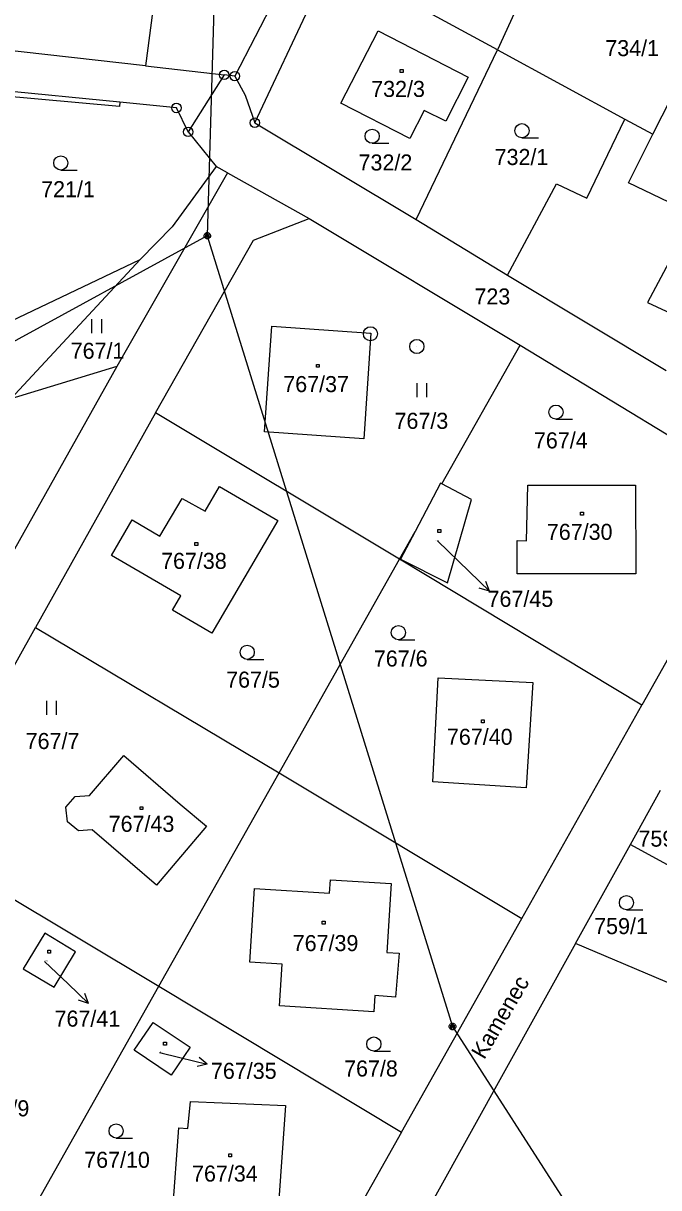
# Model space of a CAD drawing. Extents: x -468021 to -466942, y -1130484 to -1128584.
# Drawn here: x -467079.9 to -467012.6, y -1128824.5 to -1128701.2 of the extents above; entities that cross this region are included whole.
import ezdxf

# ---------------------------------------------------------------- set-up
doc = ezdxf.new("R2010")
doc.units = 0
doc.layers.add('DKM', color=7, linetype='Continuous')

msp = doc.modelspace()

# ---------------------------------------------------------------- linework, layer by layer
at = {"layer": 'DKM'}
for p, q in [((-467058.09, -1128643.52), (-467060.41, -1128723.66)), ((-467062.73, -1128674.01), (-467066.96, -1128705.68)), ((-467047.04, -1128686.61), (-467057.5, -1128706.75)), ((-467024.44, -1128692.54), (-467029.67, -1128703.98)), ((-467055.38, -1128711.69), (-467047.24, -1128694.42)), ((-467029.67, -1128703.98), (-467047.24, -1128694.42)), ((-467069.67, -1128709.53), (-467164, -1128700.1)), ((-467046.25, -1128709.61), (-467042.32, -1128701.97)), ((-467042.32, -1128701.97), (-467032.77, -1128706.88)), ((-467066.96, -1128705.68), (-467084.53, -1128703.69)), ((-467038.3, -1128721.94), (-467029.67, -1128703.98)), ((-467029.67, -1128703.98), (-467016.2, -1128711.3)), ((-467066.96, -1128705.68), (-467058.61, -1128706.63)), ((-467039.98, -1128706.07), (-467039.68, -1128706.07)), ((-467039.98, -1128706.37), (-467039.98, -1128706.07)), ((-467039.68, -1128706.07), (-467039.68, -1128706.37)), ((-467058.61, -1128706.63), (-467062.44, -1128712.66)), ((-467057.5, -1128706.75), (-467058.61, -1128706.63)), ((-467057.5, -1128706.75), (-467056.38, -1128708.77)), ((-467039.68, -1128706.37), (-467039.98, -1128706.37)), ((-467032.77, -1128706.88), (-467035.15, -1128711.51)), ((-467013.23, -1128712.92), (-467010.27, -1128707.07)), ((-467069.72, -1128709.99), (-467084.9, -1128708.58)), ((-467069.67, -1128709.53), (-467069.72, -1128709.99)), ((-467063.67, -1128710.13), (-467069.67, -1128709.53)), ((-467056.38, -1128708.77), (-467055.38, -1128711.69)), ((-467038.97, -1128713.35), (-467046.25, -1128709.61)), ((-467062.44, -1128712.66), (-467063.67, -1128710.13)), ((-467037.45, -1128710.39), (-467038.97, -1128713.35)), ((-467035.15, -1128711.51), (-467037.45, -1128710.39)), ((-467055.38, -1128711.69), (-467038.3, -1128721.94)), ((-467020.22, -1128719.68), (-467016.2, -1128711.3)), ((-467016.2, -1128711.3), (-467013.23, -1128712.92)), ((-467062.44, -1128712.66), (-467059.46, -1128716.33)), ((-467027.09, -1128713.29), (-467025.34, -1128713.29)), ((-467015.82, -1128718.04), (-467013.23, -1128712.92)), ((-467042.95, -1128713.87), (-467041.2, -1128713.87)), ((-467075.92, -1128716.7), (-467074.17, -1128716.7)), ((-467058.25, -1128717.01), (-467069.98, -1128737.5)), ((-467059.46, -1128716.33), (-467064.12, -1128722.7)), ((-467058.25, -1128717.01), (-467059.46, -1128716.33)), ((-467058.25, -1128717.01), (-467049.63, -1128721.85)), ((-467028.6, -1128727.82), (-467023.42, -1128718.15)), ((-467023.42, -1128718.15), (-467020.22, -1128719.68)), ((-467009.33, -1128721.17), (-467015.82, -1128718.04)), ((-467055.51, -1128724.12), (-467049.63, -1128721.85)), ((-467049.63, -1128721.85), (-467027.27, -1128735.26)), ((-467038.3, -1128721.94), (-467028.6, -1128727.82)), ((-467064.12, -1128722.7), (-467067.5, -1128726.17)), ((-467060.74, -1128723.59), (-467060.68, -1128723.46)), ((-467060.68, -1128723.46), (-467060.61, -1128723.39)), ((-467060.61, -1128723.39), (-467060.48, -1128723.32)), ((-467060.61, -1128723.53), (-467060.61, -1128723.79)), ((-467060.48, -1128723.32), (-467060.34, -1128723.32)), ((-467060.48, -1128723.86), (-467060.48, -1128723.46)), ((-467060.48, -1128723.46), (-467060.34, -1128723.46)), ((-467060.34, -1128723.32), (-467060.21, -1128723.39)), ((-467060.34, -1128723.46), (-467060.34, -1128723.86)), ((-467060.21, -1128723.39), (-467060.14, -1128723.46)), ((-467060.21, -1128723.79), (-467060.21, -1128723.53)), ((-467060.14, -1128723.46), (-467060.08, -1128723.59)), ((-467060.41, -1128723.66), (-467130.16, -1128761.74)), ((-467065.88, -1128742.42), (-467055.51, -1128724.12)), ((-467060.74, -1128723.73), (-467060.74, -1128723.59)), ((-467060.68, -1128723.86), (-467060.74, -1128723.73)), ((-467060.61, -1128723.93), (-467060.68, -1128723.86)), ((-467060.61, -1128723.79), (-467060.48, -1128723.86)), ((-467060.48, -1128724), (-467060.61, -1128723.93)), ((-467060.34, -1128724), (-467060.48, -1128724)), ((-467060.41, -1128723.66), (-467034.44, -1128807.4)), ((-467060.34, -1128723.86), (-467060.21, -1128723.79)), ((-467060.21, -1128723.93), (-467060.34, -1128724)), ((-467060.14, -1128723.86), (-467060.21, -1128723.93)), ((-467060.08, -1128723.73), (-467060.14, -1128723.86)), ((-467060.08, -1128723.59), (-467060.08, -1128723.73)), ((-467010.39, -1128724.39), (-467013.78, -1128730.72)), ((-467085.21, -1128734.6), (-467067.5, -1128726.17)), ((-467081.2, -1128740.93), (-467067.5, -1128726.17)), ((-467028.6, -1128727.82), (-467011.81, -1128737.92)), ((-467013.78, -1128730.72), (-467009.2, -1128732.86)), ((-467072.62, -1128733.99), (-467072.62, -1128732.49)), ((-467071.62, -1128732.49), (-467071.62, -1128733.99)), ((-467054.35, -1128744.42), (-467053.58, -1128733.24)), ((-467053.58, -1128733.24), (-467043.09, -1128733.96)), ((-467043.09, -1128733.96), (-467043.82, -1128745.18)), ((-467035.56, -1128749.94), (-467027.27, -1128735.26)), ((-467027.27, -1128735.26), (-467006.82, -1128747.7)), ((-467069.98, -1128737.5), (-467087.84, -1128769.34)), ((-467069.98, -1128737.5), (-467081.2, -1128740.93)), ((-467048.85, -1128737.28), (-467048.55, -1128737.28)), ((-467048.85, -1128737.58), (-467048.85, -1128737.28)), ((-467048.55, -1128737.58), (-467048.85, -1128737.58)), ((-467048.55, -1128737.28), (-467048.55, -1128737.58)), ((-467038.2, -1128740.76), (-467038.2, -1128739.26)), ((-467037.2, -1128739.26), (-467037.2, -1128740.76)), ((-467065.88, -1128742.42), (-467078.6, -1128765.14)), ((-467040.05, -1128757.9), (-467065.88, -1128742.42)), ((-467023.49, -1128743.09), (-467021.74, -1128743.09)), ((-467043.82, -1128745.18), (-467054.35, -1128744.42)), ((-467060.63, -1128752.84), (-467059.1, -1128750.22)), ((-467059.1, -1128750.22), (-467052.93, -1128753.8)), ((-467035.7, -1128749.87), (-467038.39, -1128754.97)), ((-467035.56, -1128749.94), (-467035.7, -1128749.87)), ((-467032.44, -1128751.58), (-467035.56, -1128749.94)), ((-467026.6, -1128755.96), (-467026.48, -1128750.08)), ((-467026.48, -1128750.08), (-467015.05, -1128750.06)), ((-467015.05, -1128750.06), (-467015.03, -1128759.45)), ((-467065.42, -1128755.48), (-467063.08, -1128751.49)), ((-467063.08, -1128751.49), (-467060.63, -1128752.84)), ((-467034.96, -1128760.43), (-467032.44, -1128751.58)), ((-467020.87, -1128752.94), (-467020.57, -1128752.94)), ((-467020.87, -1128753.24), (-467020.87, -1128752.94)), ((-467020.57, -1128752.94), (-467020.57, -1128753.24)), ((-467070.54, -1128757.52), (-467068.35, -1128753.76)), ((-467068.35, -1128753.76), (-467065.42, -1128755.48)), ((-467052.93, -1128753.8), (-467059.91, -1128765.75)), ((-467020.57, -1128753.24), (-467020.87, -1128753.24)), ((-467040.05, -1128757.9), (-467038.39, -1128754.97)), ((-467038.39, -1128754.97), (-467039.95, -1128757.91)), ((-467035.99, -1128754.78), (-467035.69, -1128754.78)), ((-467035.99, -1128755.08), (-467035.99, -1128754.78)), ((-467035.69, -1128755.08), (-467035.99, -1128755.08)), ((-467035.69, -1128754.78), (-467035.69, -1128755.08)), ((-467061.72, -1128756.15), (-467061.42, -1128756.15)), ((-467061.72, -1128756.45), (-467061.72, -1128756.15)), ((-467061.42, -1128756.45), (-467061.72, -1128756.45)), ((-467061.42, -1128756.15), (-467061.42, -1128756.45)), ((-467036.02, -1128755.97), (-467032.69, -1128759.22)), ((-467027.61, -1128759.46), (-467027.61, -1128755.94)), ((-467027.61, -1128755.94), (-467026.6, -1128755.96)), ((-467063.21, -1128761.8), (-467070.54, -1128757.52)), ((-467052.8, -1128780.54), (-467040.05, -1128757.9)), ((-467014.38, -1128773.37), (-467040.05, -1128757.9)), ((-467039.95, -1128757.91), (-467034.96, -1128760.43)), ((-467005.41, -1128757.34), (-467014.38, -1128773.37)), ((-467032.69, -1128759.22), (-467030.54, -1128761.31)), ((-467030.54, -1128761.31), (-467030.91, -1128760.26)), ((-467015.03, -1128759.45), (-467027.61, -1128759.46)), ((-467030.54, -1128761.31), (-467031.61, -1128760.97)), ((-467064.09, -1128763.31), (-467063.21, -1128761.8)), ((-467059.91, -1128765.75), (-467064.09, -1128763.31)), ((-467091.28, -1128787.7), (-467078.6, -1128765.14)), ((-467078.6, -1128765.14), (-467052.8, -1128780.54)), ((-467040.17, -1128766.44), (-467038.42, -1128766.44)), ((-467056.18, -1128768.52), (-467054.43, -1128768.52)), ((-467036.51, -1128781.49), (-467035.95, -1128770.48)), ((-467035.95, -1128770.48), (-467025.93, -1128770.99)), ((-467025.93, -1128770.99), (-467026.63, -1128782.12)), ((-467077.4, -1128774.4), (-467077.4, -1128772.9)), ((-467076.4, -1128772.9), (-467076.4, -1128774.4)), ((-467027.1, -1128795.95), (-467014.38, -1128773.37)), ((-467031.38, -1128774.93), (-467031.08, -1128774.93)), ((-467031.38, -1128775.23), (-467031.38, -1128774.93)), ((-467031.08, -1128775.23), (-467031.38, -1128775.23)), ((-467031.08, -1128774.93), (-467031.08, -1128775.23)), ((-467072.89, -1128782.93), (-467069.25, -1128778.71)), ((-467069.25, -1128778.71), (-467063.27, -1128783.87)), ((-467065.53, -1128803.14), (-467052.8, -1128780.54)), ((-467052.8, -1128780.54), (-467027.1, -1128795.95)), ((-467026.63, -1128782.12), (-467036.51, -1128781.49)), ((-467015.59, -1128788.12), (-467012.4, -1128782.36)), ((-467075.37, -1128784.18), (-467074.38, -1128783.06)), ((-467074.38, -1128783.06), (-467072.89, -1128782.93)), ((-467063.27, -1128783.87), (-467060.48, -1128786.18)), ((-467075.22, -1128785.72), (-467075.37, -1128784.18)), ((-467067.52, -1128784.13), (-467067.22, -1128784.13)), ((-467067.52, -1128784.43), (-467067.52, -1128784.13)), ((-467067.22, -1128784.43), (-467067.52, -1128784.43)), ((-467067.22, -1128784.13), (-467067.22, -1128784.43)), ((-467074.05, -1128786.69), (-467075.22, -1128785.72)), ((-467060.48, -1128786.18), (-467065.78, -1128792.42)), ((-467072.59, -1128786.57), (-467074.05, -1128786.69)), ((-467068.59, -1128790.04), (-467072.59, -1128786.57)), ((-467091.28, -1128787.7), (-467065.53, -1128803.14)), ((-467021.4, -1128798.6), (-467015.59, -1128788.12)), ((-467015.59, -1128788.12), (-467009.42, -1128791.52)), ((-467065.78, -1128792.42), (-467068.59, -1128790.04)), ((-467047.46, -1128793.3), (-467047.37, -1128791.86)), ((-467047.37, -1128791.86), (-467040.92, -1128792.27)), ((-467040.92, -1128792.27), (-467041.38, -1128799.56)), ((-467055.9, -1128800.58), (-467055.4, -1128792.79)), ((-467055.4, -1128792.79), (-467047.46, -1128793.3)), ((-467016.02, -1128795.04), (-467014.27, -1128795.04)), ((-467048.24, -1128796.26), (-467047.94, -1128796.26)), ((-467048.24, -1128796.56), (-467048.24, -1128796.26)), ((-467047.94, -1128796.26), (-467047.94, -1128796.56)), ((-467039.84, -1128818.58), (-467027.1, -1128795.95)), ((-467077.62, -1128797.52), (-467079.89, -1128801.3)), ((-467074.36, -1128799.48), (-467077.62, -1128797.52)), ((-467047.94, -1128796.56), (-467048.24, -1128796.56)), ((-467021.4, -1128798.6), (-467036.38, -1128825.6)), ((-467004.41, -1128805.84), (-467021.4, -1128798.6)), ((-467077.3, -1128799.33), (-467077, -1128799.33)), ((-467077.3, -1128799.63), (-467077.3, -1128799.33)), ((-467077, -1128799.63), (-467077.3, -1128799.63)), ((-467077, -1128799.33), (-467077, -1128799.63)), ((-467076.63, -1128803.25), (-467074.36, -1128799.48)), ((-467041.38, -1128799.56), (-467040.09, -1128799.65)), ((-467040.09, -1128799.65), (-467040.48, -1128804.3)), ((-467077.65, -1128800.51), (-467075.15, -1128802.89)), ((-467052.47, -1128800.8), (-467055.9, -1128800.58)), ((-467052.75, -1128805.22), (-467052.47, -1128800.8)), ((-467079.89, -1128801.3), (-467076.63, -1128803.25)), ((-467078.27, -1128825.75), (-467065.53, -1128803.14)), ((-467075.15, -1128802.89), (-467072.98, -1128804.96)), ((-467065.53, -1128803.14), (-467039.84, -1128818.58)), ((-467072.98, -1128804.96), (-467074.05, -1128804.63)), ((-467072.98, -1128804.96), (-467073.36, -1128803.91)), ((-467042.67, -1128804.11), (-467042.78, -1128805.85)), ((-467040.48, -1128804.3), (-467042.67, -1128804.11)), ((-467042.78, -1128805.85), (-467052.75, -1128805.22)), ((-467068.14, -1128809.9), (-467066.14, -1128806.97)), ((-467066.14, -1128806.97), (-467062.22, -1128809.61)), ((-467034.78, -1128807.33), (-467034.71, -1128807.2)), ((-467034.78, -1128807.47), (-467034.78, -1128807.33)), ((-467034.71, -1128807.2), (-467034.64, -1128807.13)), ((-467034.64, -1128807.13), (-467034.51, -1128807.06)), ((-467034.64, -1128807.27), (-467034.64, -1128807.53)), ((-467034.51, -1128807.06), (-467034.37, -1128807.06)), ((-467034.51, -1128807.6), (-467034.51, -1128807.2)), ((-467034.51, -1128807.2), (-467034.37, -1128807.2)), ((-467034.44, -1128807.4), (-466972.37, -1128904.07)), ((-467034.37, -1128807.06), (-467034.24, -1128807.13)), ((-467034.37, -1128807.2), (-467034.37, -1128807.6)), ((-467034.24, -1128807.13), (-467034.17, -1128807.2)), ((-467034.24, -1128807.53), (-467034.24, -1128807.27)), ((-467034.17, -1128807.2), (-467034.1, -1128807.33)), ((-467034.1, -1128807.33), (-467034.1, -1128807.47)), ((-467034.71, -1128807.6), (-467034.78, -1128807.47)), ((-467034.64, -1128807.67), (-467034.71, -1128807.6)), ((-467034.64, -1128807.53), (-467034.51, -1128807.6)), ((-467034.51, -1128807.74), (-467034.64, -1128807.67)), ((-467034.37, -1128807.74), (-467034.51, -1128807.74)), ((-467034.37, -1128807.6), (-467034.24, -1128807.53)), ((-467034.24, -1128807.67), (-467034.37, -1128807.74)), ((-467034.17, -1128807.6), (-467034.24, -1128807.67)), ((-467034.1, -1128807.47), (-467034.17, -1128807.6)), ((-467065.03, -1128809.08), (-467064.73, -1128809.08)), ((-467065.03, -1128809.38), (-467065.03, -1128809.08)), ((-467064.73, -1128809.38), (-467065.03, -1128809.38)), ((-467064.73, -1128809.08), (-467064.73, -1128809.38)), ((-467062.22, -1128809.61), (-467064.24, -1128812.56)), ((-467064.24, -1128812.56), (-467068.14, -1128809.9)), ((-467065.46, -1128810.17), (-467063.32, -1128810.69)), ((-467063.32, -1128810.69), (-467060.41, -1128811.4)), ((-467060.41, -1128811.4), (-467061.26, -1128810.68)), ((-467042.77, -1128810.01), (-467041.02, -1128810.01)), ((-467060.41, -1128811.4), (-467061.49, -1128811.65)), ((-467062.46, -1128818.21), (-467062.18, -1128815.33)), ((-467062.18, -1128815.33), (-467052.11, -1128815.76)), ((-467052.11, -1128815.76), (-467053.06, -1128828.72)), ((-467064.15, -1128827.91), (-467063.41, -1128818.15)), ((-467063.41, -1128818.15), (-467062.46, -1128818.21)), ((-467070.06, -1128819.22), (-467068.31, -1128819.22)), ((-467039.84, -1128818.58), (-467052.61, -1128841.21)), ((-467058.13, -1128820.89), (-467057.83, -1128820.89)), ((-467058.13, -1128821.19), (-467058.13, -1128820.89)), ((-467057.83, -1128820.89), (-467057.83, -1128821.19)), ((-467057.83, -1128821.19), (-467058.13, -1128821.19))]:
    msp.add_line(p, q, dxfattribs=at)
for centre, radius in [((-467058.61, -1128706.63), 0.5), ((-467057.5, -1128706.75), 0.5), ((-467058.61, -1128706.63), 0.01), ((-467057.5, -1128706.75), 0.01), ((-467063.67, -1128710.13), 0.5), ((-467063.67, -1128710.13), 0.01), ((-467055.38, -1128711.69), 0.5), ((-467062.44, -1128712.66), 0.5), ((-467055.38, -1128711.69), 0.01), ((-467042.95, -1128713.12), 0.75), ((-467027.09, -1128712.54), 0.75), ((-467062.44, -1128712.66), 0.01), ((-467075.92, -1128715.95), 0.75), ((-467043.13, -1128734.04), 0.75), ((-467043.13, -1128734.04), 0.01), ((-467038.22, -1128735.39), 0.75), ((-467038.22, -1128735.39), 0.01), ((-467023.49, -1128742.34), 0.75), ((-467040.17, -1128765.69), 0.75), ((-467056.18, -1128767.77), 0.75), ((-467016.02, -1128794.29), 0.75), ((-467042.77, -1128809.26), 0.75), ((-467070.06, -1128818.47), 0.75)]:
    msp.add_circle(centre, radius, dxfattribs=at)

# ---------------------------------------------------------------- texts
for s, height, p in [('734/1', 1.7, (-467018.26, -1128704.64)), ('732/3', 1.7, (-467043.05, -1128708.96)), ('732/1', 1.7, (-467029.98, -1128716.17)), ('732/2', 1.7, (-467044.39, -1128716.75)), ('721/1', 1.7, (-467078, -1128719.58)), ('723', 1.7, (-467032.12, -1128730.94)), ('767/1', 1.7, (-467074.87, -1128736.69)), ('767/37', 1.7, (-467052.36, -1128740.22)), ('767/3', 1.7, (-467040.58, -1128744.11)), ('767/4', 1.7, (-467025.82, -1128746.18)), ('767/30', 1.7, (-467024.45, -1128755.87)), ('767/45', 0.1, (-467036.28, -1128755.97)), ('767/38', 1.7, (-467065.3, -1128758.94)), ('767/45', 1.7, (-467030.73, -1128762.96)), ('767/6', 1.7, (-467042.77, -1128769.28)), ('767/5', 1.7, (-467058.41, -1128771.52)), ('767/7', 1.7, (-467079.64, -1128778.02)), ('767/40', 1.7, (-467035.03, -1128777.57)), ('767/43', 1.7, (-467070.85, -1128786.79)), ('759/2', 1.7, (-467014.75, -1128788.36)), ('759/1', 1.7, (-467019.44, -1128797.62)), ('767/39', 1.7, (-467051.36, -1128799.42)), ('767/41', 0.1, (-467077.65, -1128800.51)), ('767/41', 1.7, (-467076.58, -1128807.42)), ('767/35', 0.1, (-467065.46, -1128810.17)), ('767/8', 1.7, (-467045.92, -1128812.7)), ('767/35', 1.7, (-467060.02, -1128812.95)), ('767/9', 1.7, (-467084.94, -1128816.92)), ('767/10', 1.7, (-467073.44, -1128822.37)), ('767/34', 1.7, (-467062.02, -1128823.83))]:
    msp.add_text(s, height=height, dxfattribs=at).set_placement(p)
msp.add_text('Kamenec', height=1.7, rotation=59.7802, dxfattribs=at).set_placement((-467031.08, -1128810.98))

doc.saveas('drawing.dxf')
